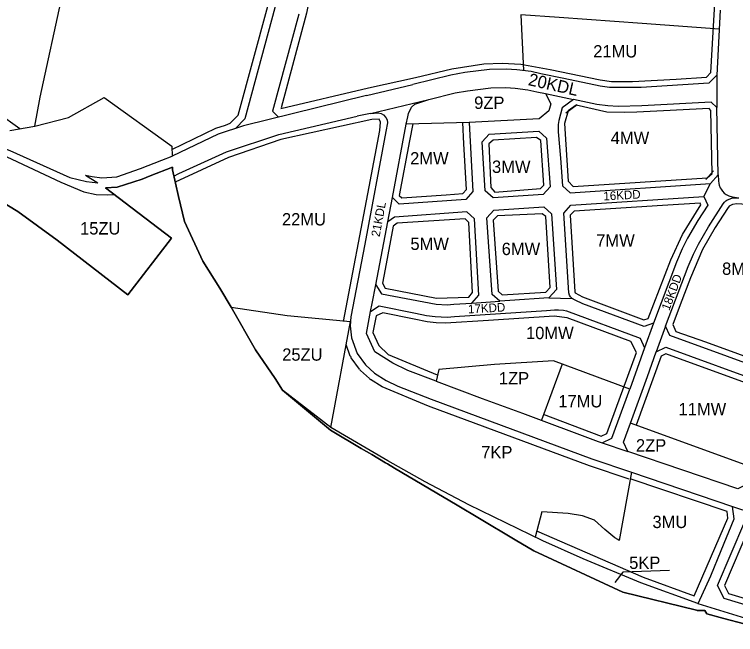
# Model space of a CAD drawing. Extents: x 7428203 to 7432868, y 5542672 to 5545406.
# Drawn here: x 7431420 to 7432004, y 5542894 to 5543396 of the extents above; entities that cross this region are included whole.
import ezdxf

# ---------------------------------------------------------------- set-up
doc = ezdxf.new("R2010")
doc.units = 0
for name, color, linetype in [('__LEGENDA_RAMKA_LOGO_PODZIAŁKA', 7, 'Continuous'), ('_GRANICA_MIASTA', 7, 'Continuous'), ('granicaBulwary', 7, 'Continuous'), ('MPZP_uchwalone_nieobowiazujace jeszcze_SZRAF', 7, 'Continuous')]:
    doc.layers.add(name, color=color, linetype=linetype)

msp = doc.modelspace()

# ---------------------------------------------------------------- linework, layer by layer
at = {"layer": '__LEGENDA_RAMKA_LOGO_PODZIAŁKA'}
msp.add_lwpolyline([(7431389.74, 5543255.95), (7431422.59, 5543236.25), (7431454.36, 5543213.02), (7431511.7, 5543168.81), (7431547.16, 5543214.78), (7431493.62, 5543255.54), (7431503.11, 5543255.89), (7431523.35, 5543262.55), (7431529.68, 5543265.09), (7431547.71, 5543272.32), (7431547.71, 5543271.92), (7431547.72, 5543271.35), (7431547.75, 5543269.92), (7431552.77, 5543248.55), (7431557.55, 5543228.24), (7431572.47, 5543195.93), (7431586.13, 5543174.25), (7431595.28, 5543158.86), (7431615.19, 5543124.31), (7431630.97, 5543100.97), (7431637.05, 5543091.63), (7431675.9, 5543059.21), (7431700.89, 5543044.38), (7431709.41, 5543039.33), (7431720.58, 5543032.7), (7431722.11, 5543031.79), (7431727.75, 5543028.47), (7431778.7, 5542998.39), (7431796.77, 5542987.57), (7431825.57, 5542970.33), (7431840.69, 5542961.29), (7431912.76, 5542927.96), (7431972.47, 5542913.23), (7431973.07, 5542913.08), (7431979.3, 5542912.96), (7431980.87, 5542910.28), (7431994.8, 5542906.65), (7432011.22, 5542902.36)], dxfattribs=at)
at = {"layer": '_GRANICA_MIASTA'}
for p, q in [((7431650.15, 5543396.15), (7431628.87, 5543317.63)), ((7431991.84, 5543399.38), (7431988.98, 5543346.68)), ((7431784.79, 5543349.01), (7431773.48, 5543346.73)), ((7431804.81, 5543351.43), (7431784.79, 5543349.01)), ((7431818.35, 5543351.62), (7431804.81, 5543351.43)), ((7431826.9, 5543351.11), (7431818.35, 5543351.62)), ((7431838.44, 5543349.6), (7431826.9, 5543351.11)), ((7431846.26, 5543347.95), (7431838.44, 5543349.6)), ((7431865.06, 5543343.99), (7431846.26, 5543347.95)), ((7431773.48, 5543346.73), (7431742.73, 5543339.14)), ((7431894.42, 5543337.81), (7431865.06, 5543343.99)), ((7431988.98, 5543346.68), (7431982.63, 5543340.29)), ((7431704.98, 5543330.36), (7431742.73, 5543339.14)), ((7431787.04, 5543334.17), (7431805.82, 5543336.44)), ((7431805.82, 5543336.44), (7431818.01, 5543336.62)), ((7431818.01, 5543336.62), (7431825.48, 5543336.17)), ((7431825.48, 5543336.17), (7431835.92, 5543334.8)), ((7431902.1, 5543336.77), (7431894.42, 5543337.81)), ((7431927.62, 5543336.75), (7431902.1, 5543336.77)), ((7431982.63, 5543340.29), (7431927.62, 5543336.75)), ((7431704.98, 5543330.36), (7431605.47, 5543305.81)), ((7431755.54, 5543326.92), (7431776.87, 5543332.31)), ((7431776.87, 5543332.31), (7431787.04, 5543334.17)), ((7431835.92, 5543334.8), (7431843.17, 5543333.27)), ((7431843.17, 5543333.27), (7431850.09, 5543331.81)), ((7431850.09, 5543331.81), (7431872.83, 5543327.03)), ((7431850.09, 5543331.81), (7431854.37, 5543323.64)), ((7431708.38, 5543315.74), (7431755.54, 5543326.92)), ((7431744.38, 5543323.34), (7431755.54, 5543326.92)), ((7431739.11, 5543315.76), (7431741.63, 5543320.87)), ((7431741.63, 5543320.87), (7431744.38, 5543323.34)), ((7431854.37, 5543323.64), (7431852.77, 5543317.91)), ((7431628.96, 5543317.55), (7431633.8, 5543312.8)), ((7431708.38, 5543315.74), (7431697.64, 5543313.47)), ((7431708.38, 5543315.74), (7431714.42, 5543316.36)), ((7431714.42, 5543316.36), (7431716.87, 5543315.78)), ((7431716.87, 5543315.78), (7431718.9, 5543314.51)), ((7431718.9, 5543314.51), (7431720.73, 5543312.55)), ((7431720.73, 5543312.55), (7431721.82, 5543310.61)), ((7431737.2, 5543307.03), (7431738.59, 5543313.05)), ((7431738.59, 5543313.05), (7431739.11, 5543315.76)), ((7431852.77, 5543317.91), (7431845.04, 5543311.44)), ((7431722.15, 5543308.2), (7431720.88, 5543301)), ((7431721.82, 5543310.61), (7431722.15, 5543308.2)), ((7431726.17, 5543247.73), (7431737.2, 5543307.03)), ((7431788.19, 5543308.51), (7431737.2, 5543307.03)), ((7431845.04, 5543311.44), (7431788.19, 5543308.51)), ((7431788.19, 5543308.51), (7431791.27, 5543252.4)), ((7431605.47, 5543305.81), (7431584.92, 5543299.03)), ((7431720.88, 5543301), (7431703.66, 5543209.89)), ((7431584.92, 5543299.03), (7431547.5, 5543281)), ((7431547.71, 5543272.32), (7431529.68, 5543265.09)), ((7431547.71, 5543271.92), (7431547.71, 5543272.32)), ((7431547.72, 5543271.35), (7431547.71, 5543271.92)), ((7431547.75, 5543269.92), (7431547.72, 5543271.35)), ((7431477.33, 5543265.7), (7431487.44, 5543259.4)), ((7431552.77, 5543248.55), (7431547.75, 5543269.92)), ((7431523.35, 5543262.55), (7431503.11, 5543255.89)), ((7431529.68, 5543265.09), (7431523.35, 5543262.55)), ((7431422.59, 5543236.25), (7431389.74, 5543255.95)), ((7431503.11, 5543255.89), (7431493.62, 5543255.54)), ((7431493.62, 5543255.54), (7431547.16, 5543214.78)), ((7431978.52, 5543248.35), (7431983.83, 5543258.99)), ((7431557.55, 5543228.24), (7431552.77, 5543248.55)), ((7431791.27, 5543252.4), (7431785.69, 5543245.99)), ((7431722.36, 5543227.81), (7431726.17, 5543247.73)), ((7431731.52, 5543242.13), (7431726.17, 5543247.73)), ((7431785.69, 5543245.99), (7431731.52, 5543242.13)), ((7431454.36, 5543213.02), (7431422.59, 5543236.25)), ((7431572.47, 5543195.93), (7431557.55, 5543228.24)), ((7431712.61, 5543176.78), (7431722.36, 5543227.81)), ((7431511.7, 5543168.81), (7431454.36, 5543213.02)), ((7431547.16, 5543214.78), (7431511.7, 5543168.81)), ((7431703.66, 5543209.89), (7431692.26, 5543150.94)), ((7431586.13, 5543174.25), (7431572.47, 5543195.93)), ((7431595.28, 5543158.86), (7431586.13, 5543174.25)), ((7431709.72, 5543161.69), (7431712.61, 5543176.78)), ((7431708.45, 5543155.18), (7431709.72, 5543161.69)), ((7431615.19, 5543124.31), (7431595.28, 5543158.86)), ((7431705.12, 5543137.59), (7431708.45, 5543155.18)), ((7431676.21, 5543061.35), (7431691.99, 5543147.31)), ((7431937.69, 5543145.87), (7431930.46, 5543125.87)), ((7431711.76, 5543122.53), (7431705.12, 5543137.59)), ((7431630.97, 5543100.97), (7431615.19, 5543124.31)), ((7431863.58, 5543112.73), (7431846.95, 5543067.25)), ((7431637.05, 5543091.63), (7431630.97, 5543100.97)), ((7431721, 5543099.47), (7431730.42, 5543094.82)), ((7431675.9, 5543059.21), (7431637.05, 5543091.63)), ((7431730.42, 5543094.82), (7431757.44, 5543084.31)), ((7431757.44, 5543084.31), (7431887.8, 5543035.86)), ((7432017.85, 5543028.79), (7431919, 5543064.95)), ((7431700.89, 5543044.38), (7431675.9, 5543059.21)), ((7431709.41, 5543039.33), (7431700.89, 5543044.38)), ((7431896.06, 5543048.9), (7431916.9, 5543041.85)), ((7431720.58, 5543032.7), (7431709.41, 5543039.33)), ((7431722.11, 5543031.79), (7431720.58, 5543032.7)), ((7431727.75, 5543028.47), (7431722.11, 5543031.79)), ((7431887.8, 5543035.86), (7431919.79, 5543025.03)), ((7431778.7, 5542998.39), (7431727.75, 5543028.47)), ((7431919.79, 5543025.03), (7431909.97, 5542969.91)), ((7431796.77, 5542987.57), (7431778.7, 5542998.39)), ((7432001.68, 5542997.32), (7432063.09, 5542976.74)), ((7431825.57, 5542970.33), (7431796.77, 5542987.57)), ((7431989.67, 5542933.23), (7432011.78, 5542985.25)), ((7431840.69, 5542961.29), (7431825.57, 5542970.33)), ((7431912.76, 5542927.96), (7431840.69, 5542961.29)), ((7431995.04, 5542922.73), (7431989.67, 5542933.23)), ((7431972.47, 5542913.23), (7431912.76, 5542927.96)), ((7432019.53, 5542915.43), (7431995.04, 5542922.73)), ((7431973.07, 5542913.08), (7431972.47, 5542913.23)), ((7431979.3, 5542912.96), (7431973.07, 5542913.08)), ((7431980.87, 5542910.28), (7431979.3, 5542912.96)), ((7431994.8, 5542906.65), (7431980.87, 5542910.28)), ((7432011.22, 5542902.36), (7431994.8, 5542906.65))]:
    msp.add_line(p, q, dxfattribs=at)
for points in [[(7431436.3, 5543305.53), (7431440.68, 5543328.86), (7431476.66, 5543495.49), (7431506.81, 5543625.52)], [(7431667.23, 5543590.08), (7431645.7, 5543477.8), (7431630.84, 5543401.36), (7431606.51, 5543311.31), (7431598.84, 5543303.62)], [(7431991, 5543383.88), (7431928.42, 5543388.5), (7431861.27, 5543393.45), (7431830.25, 5543395.73), (7431832.25, 5543350.41)], [(7431988.98, 5543346.68), (7431989.03, 5543320.57), (7431984.56, 5543324.99), (7431928.27, 5543321.77), (7431909.17, 5543321.34), (7431900.66, 5543321.83), (7431891.87, 5543323.02), (7431872.83, 5543327.03), (7431863.73, 5543320.36), (7431861.05, 5543309.9), (7431860.44, 5543306.88), (7431860.38, 5543306.1), (7431860.47, 5543300.79), (7431862.3, 5543279.55), (7431863.93, 5543256.98), (7431870.26, 5543251.36), (7431983.83, 5543258.99), (7431990.16, 5543266.02), (7431989.49, 5543292.86), (7431989.03, 5543320.57)], [(7431415.94, 5543301.93), (7431436.35, 5543305.54), (7431463.65, 5543312.41), (7431492.57, 5543328.57), (7431547.32, 5543289.35), (7431547.5, 5543281)], [(7431591.58, 5543284.69), (7431634.06, 5543298.65), (7431697.64, 5543313.47)], [(7431383.66, 5543294.77), (7431401.55, 5543290.86), (7431416.06, 5543285.83), (7431464.51, 5543263.85), (7431478.05, 5543260.69), (7431487.44, 5543259.4)], [(7431384.15, 5543294.67), (7431390.98, 5543291.05), (7431457.43, 5543259.96)], [(7431548.9, 5543265.04), (7431553.05, 5543267.04), (7431591.58, 5543284.69)], [(7431477.33, 5543265.7), (7431482.72, 5543264.73), (7431490.43, 5543263.67), (7431502.66, 5543264.27), (7431521.83, 5543271.16), (7431539.28, 5543278), (7431547.5, 5543281)], [(7431990.16, 5543266.02), (7431990.37, 5543261.06), (7431990.58, 5543259.1), (7431990.97, 5543257.51), (7431991.75, 5543255.57), (7431992.43, 5543254.34), (7431993.59, 5543252.77), (7431995.11, 5543251.25), (7431996.69, 5543250.09), (7431998.75, 5543249.03), (7432001.46, 5543248.23), (7432006.98, 5543247.37)], [(7431457.43, 5543259.96), (7431475.95, 5543252.27), (7431486.04, 5543250.05), (7431495.11, 5543249.75), (7431500.69, 5543250.16)], [(7431852.94, 5543166.25), (7431871.67, 5543165.86), (7431870.35, 5543167.08), (7431869.56, 5543168.57), (7431869.08, 5543170.32), (7431865.01, 5543235), (7431870.79, 5543241.37), (7431978.52, 5543248.35), (7431981.64, 5543241.54), (7431973.75, 5543229.07), (7431965.27, 5543214.61), (7431961.01, 5543205.95), (7431956.42, 5543195.38), (7431937.69, 5543145.87), (7431930.2, 5543143.04), (7431880.3, 5543161.59), (7431874.35, 5543164.47), (7431871.67, 5543165.86)], [(7432032.45, 5543106.16), (7431997.81, 5543118.94), (7431950.96, 5543135.72), (7431947.45, 5543143.42), (7431965.69, 5543191.62), (7431970.09, 5543201.75), (7431974.08, 5543209.86), (7431982.29, 5543223.86), (7431994.13, 5543242.58), (7431995.19, 5543243.87), (7431996.41, 5543244.83), (7431997.28, 5543245.45), (7431999.07, 5543246.35), (7432001.23, 5543246.99), (7432003.48, 5543247.42), (7432006.98, 5543247.37)], [(7431790.38, 5543162.09), (7431813.29, 5543163.58), (7431806.9, 5543169.18), (7431802.72, 5543231.14), (7431808.31, 5543237.5), (7431848.84, 5543240.01), (7431855.15, 5543234.39), (7431858.96, 5543173.07), (7431852.94, 5543166.25), (7431821.28, 5543164.1), (7431813.29, 5543163.58)], [(7431712.61, 5543176.78), (7431717.36, 5543169.7), (7431761.61, 5543161.14), (7431770.39, 5543160.8), (7431775.88, 5543161.15), (7431790.38, 5543162.09), (7431796.13, 5543168.48), (7431792.75, 5543230.45), (7431786.36, 5543236.01), (7431727.71, 5543231.83), (7431722.36, 5543227.81)], [(7431595.28, 5543158.86), (7431640.84, 5543152.09), (7431691.99, 5543147.31)], [(7431708.45, 5543155.18), (7431715.48, 5543159.88), (7431744.71, 5543153.96), (7431753.69, 5543152.14), (7431760.73, 5543151.17), (7431770.52, 5543150.78), (7431776.53, 5543151.17), (7431850.99, 5543156.01), (7431857.35, 5543156.63), (7431860.71, 5543156.74), (7431864.67, 5543156.37), (7431867.13, 5543155.82), (7431926.83, 5543133.62), (7431930.46, 5543125.87), (7431918.41, 5543092.32), (7431856.75, 5543115.27), (7431808.89, 5543112.26), (7431763.62, 5543108.23), (7431761.6, 5543098.78), (7431738.65, 5543107.49), (7431726.48, 5543113.5), (7431711.76, 5543122.53)], [(7431692.26, 5543150.94), (7431691.71, 5543143.67), (7431693.03, 5543134.07), (7431697.59, 5543121.2), (7431704.23, 5543111.96), (7431711.5, 5543105.36), (7431721, 5543099.47)], [(7431947.45, 5543143.42), (7431939.96, 5543122.74), (7431947.58, 5543126.31), (7432030.55, 5543096.2), (7432035.1, 5543088.13), (7432028.11, 5543060.23), (7432017.85, 5543028.79), (7432013.51, 5543015.49), (7432005.96, 5543011.7), (7431916.9, 5543041.85), (7431913.29, 5543049.4), (7431919, 5543064.95), (7431932.86, 5543102.67), (7431939.96, 5543122.74)], [(7431761.6, 5543098.78), (7431798.71, 5543084.7), (7431831.66, 5543073), (7431892.84, 5543049.99), (7431896.06, 5543048.9), (7431903.81, 5543052.61), (7431918.41, 5543092.32)], [(7431973.61, 5542918.72), (7431927.43, 5542935.57), (7431880.83, 5542955.06), (7431848.05, 5542969.53), (7431788, 5542998.67), (7431752.6, 5543017.22), (7431722.5, 5543034.34), (7431676.21, 5543061.35), (7431637.05, 5543091.63)], [(7431919.79, 5543025.03), (7432001.68, 5542997.32)], [(7431973.93, 5542918.62), (7431984.23, 5542941.05), (7431992.43, 5542961.69), (7432003.03, 5542987.3), (7432001.68, 5542997.32)], [(7431909.97, 5542969.91), (7431908.8, 5542970.62), (7431906.46, 5542972.01), (7431898.21, 5542978.82), (7431889.92, 5542986.2), (7431880.26, 5542989.77), (7431868.45, 5542991.54), (7431847.25, 5542993.09), (7431841.76, 5542972.58)], [(7431973.61, 5542918.72), (7432026.26, 5542902.45), (7432052.98, 5542896.69)]]:
    msp.add_lwpolyline(points, dxfattribs=at)
msp.add_lwpolyline([(7431804.45, 5543298.95), (7431844.68, 5543301.4), (7431851.1, 5543295.77), (7431853.95, 5543256.36), (7431848.3, 5543250), (7431807.64, 5543247.47), (7431801.24, 5543253.09), (7431798.95, 5543292.68)], close=True, dxfattribs=at)
msp.add_ellipse((7431629.16, 5543317.7), major_axis=(0.314, 0.013), ratio=0.643015, start_param=3.44605, end_param=3.966719, dxfattribs=at)
at = {"layer": 'granicaBulwary'}
msp.add_lwpolyline([(7431950.59, 5542945.57), (7431912.96, 5542944.04), (7431906.44, 5542935.84)], dxfattribs=at)
at = {"layer": 'MPZP_uchwalone_nieobowiazujace jeszcze_SZRAF'}
for p, q in [((7431984.1, 5543349.02), (7431988.54, 5543424.24)), ((7431774.35, 5543352), (7431800.26, 5543355.92)), ((7431800.26, 5543355.92), (7431815.15, 5543356.58)), ((7431815.15, 5543356.58), (7431830.13, 5543355.73)), ((7431830.13, 5543355.73), (7431853.94, 5543351.44)), ((7431744.68, 5543344.77), (7431774.35, 5543352)), ((7431853.94, 5543351.44), (7431894.43, 5543342.91)), ((7431980.59, 5543345.18), (7431984.1, 5543349.02)), ((7431365.58, 5543344.99), (7431424.16, 5543303.46)), ((7431706.78, 5543336.52), (7431744.68, 5543344.77)), ((7431894.43, 5543342.91), (7431903.59, 5543341.69)), ((7431903.59, 5543341.69), (7431920.61, 5543341.6)), ((7431920.61, 5543341.6), (7431955.99, 5543343.62)), ((7431955.99, 5543343.62), (7431980.59, 5543345.18)), ((7431635.66, 5543319.86), (7431706.78, 5543336.52)), ((7431866.68, 5543316.33), (7431875.79, 5543322.99)), ((7431980.12, 5543262.33), (7431986.44, 5543269.36)), ((7431691.93, 5543119.2), (7431688.57, 5543128.69)), ((7431699.35, 5543108.46), (7431692.72, 5543117.7)), ((7431707.46, 5543100.92), (7431700.19, 5543107.52)), ((7431717.84, 5543094.37), (7431708.34, 5543100.26)), ((7431755.35, 5543078.69), (7431717.84, 5543094.37)), ((7431885.71, 5543030.24), (7431755.35, 5543078.69)), ((7431917.87, 5543019.35), (7431885.88, 5543030.18))]:
    msp.add_line(p, q, dxfattribs=at)
for points in [[(7431594.59, 5543307.86), (7431601.14, 5543314.41), (7431625, 5543402.72), (7431639.8, 5543478.94), (7431661.34, 5543591.21)], [(7431694.1, 5543592.69), (7431674.64, 5543491.6), (7431660.37, 5543416.96), (7431656.51, 5543397.07), (7431635.8, 5543320.41)], [(7431547.39, 5543286.47), (7431583.04, 5543303.68), (7431590.91, 5543306.31), (7431594.59, 5543307.86)], [(7431686.51, 5543147.12), (7431707.36, 5543256.37), (7431715.97, 5543301.93), (7431716.56, 5543308.66), (7431715.25, 5543311.09), (7431709.41, 5543310.85), (7431635.75, 5543294.63), (7431593.15, 5543279.94), (7431549.9, 5543260.1)], [(7431742.58, 5543307.19), (7431739.87, 5543293.62), (7431731.52, 5543249.36), (7431733.81, 5543247.3), (7431769.63, 5543249.85), (7431783.27, 5543250.83), (7431786.15, 5543254.13), (7431784.03, 5543291.23), (7431783.19, 5543308.37)], [(7432034.39, 5543113.14), (7432043.73, 5543188.67), (7432048.44, 5543232.45), (7432044.91, 5543236.73), (7432009.4, 5543242.19), (7432005.32, 5543242.44), (7432001.75, 5543241.93), (7431999.15, 5543240.63), (7431997.6, 5543238.7), (7431987.79, 5543223.21), (7431977.48, 5543205.45), (7431967.63, 5543182.62), (7431959.31, 5543160.62), (7431953.35, 5543144.87), (7431955.89, 5543139.22), (7431979.8, 5543130.62), (7432031.84, 5543111.71), (7432034.42, 5543113.41)], [(7431899.93, 5543056.33), (7431923.81, 5543122.08), (7431919.28, 5543131.09), (7431867.71, 5543150.27), (7431857.2, 5543151.59), (7431804, 5543147.95), (7431769.07, 5543145.84), (7431761.65, 5543146.13), (7431754.37, 5543147), (7431743.62, 5543149.08), (7431718.39, 5543154.19), (7431712.87, 5543151.67), (7431710.34, 5543138.31), (7431714.98, 5543127.62), (7431722.6, 5543120.5), (7431762.28, 5543103.87)], [(7432013.15, 5543030.51), (7432029.77, 5543087.41), (7432027.1, 5543092.15), (7431947.8, 5543120.89), (7431943.97, 5543119.1), (7431923.69, 5543063.23)], [(7431848.27, 5543071.99), (7431895.3, 5543054.31), (7431899.93, 5543056.33)], [(7431997.52, 5542993.23), (7431918.84, 5543019.67)], [(7431842.83, 5542977.53), (7431929.29, 5542940.21), (7431970.57, 5542924.97), (7431997.9, 5542987.96), (7431997.34, 5542993.4)], [(7432023.88, 5542984.66), (7432015.52, 5542980.91), (7431995.17, 5542933.46), (7431998.58, 5542926.78), (7432020.96, 5542920.22), (7432052.26, 5542917.94), (7432057.44, 5542919.56), (7432066.42, 5542919.52), (7432164.7, 5542893.58)]]:
    msp.add_lwpolyline(points, dxfattribs=at)
for points in [[(7431913.93, 5543316.44), (7431899.83, 5543316.89), (7431874.9, 5543322.34), (7431868.64, 5543317.76), (7431865.7, 5543307.67), (7431868.67, 5543260.75), (7431872.52, 5543256.51), (7431981.16, 5543263.49), (7431985.13, 5543266.99), (7431984.07, 5543318.06), (7431982.7, 5543319.79), (7431945.82, 5543317.9), (7431924.13, 5543316.67)], [(7431846.48, 5543293.73), (7431842.86, 5543296.28), (7431807.79, 5543294.16), (7431804.18, 5543291.06), (7431805.75, 5543255.79), (7431809.01, 5543251.9), (7431846.1, 5543255.05), (7431848.75, 5543257.6)], [(7431976.06, 5543241.72), (7431975.54, 5543243.14), (7431944.93, 5543241.11), (7431873.44, 5543236.53), (7431870.14, 5543233.22), (7431874.05, 5543171.21), (7431874.3, 5543170.3), (7431880.24, 5543167.18), (7431929.79, 5543148.52), (7431933.41, 5543149.6), (7431951.72, 5543197.09), (7431961.25, 5543217.63)], [(7431729.84, 5543226.97), (7431726.79, 5543224.36), (7431720.12, 5543189.49), (7431717.97, 5543178.19), (7431720.29, 5543174.3), (7431761.75, 5543166.17), (7431787.94, 5543166.85), (7431791.03, 5543170.81), (7431787.94, 5543227.46), (7431785.1, 5543230.47)], [(7431811.27, 5543232.67), (7431807.67, 5543229.19), (7431811.74, 5543171.72), (7431815, 5543168.73), (7431850.47, 5543171), (7431853.89, 5543174.73), (7431850.37, 5543232.12), (7431847.57, 5543234.44)]]:
    msp.add_lwpolyline(points, close=True, dxfattribs=at)
for centre, radius, start, end in [((7431697.37, 5543121.11), 5.77, 199.32116, 216.2274), ((7431705, 5543112.67), 7.05, 216.65394, 226.9151), ((7431712.02, 5543106.08), 6.89, 228.54864, 237.71156)]:
    msp.add_arc(centre, radius, start, end, dxfattribs=at)

# ---------------------------------------------------------------- texts
at = {"layer": 'granicaBulwary'}
for s, p in [('21MU', (7431888.86, 5543361.06)), ('9ZP', (7431792.35, 5543319.41)), ('4MW', (7431903.05, 5543290.93)), ('2MW', (7431740.47, 5543274.38)), ('3MW', (7431806.83, 5543267.58)), ('22MU', (7431636.57, 5543224.98)), ('15ZU', (7431472.91, 5543217.66)), ('5MW', (7431740.67, 5543205.16)), ('7MW', (7431891.31, 5543207.84)), ('6MW', (7431814.66, 5543201.01)), ('8MW', (7431993.29, 5543184.98)), ('10MW', (7431834.39, 5543132.89)), ('25ZU', (7431636.74, 5543115.43)), ('1ZP', (7431812.39, 5543096.23)), ('17MU', (7431860.57, 5543077.59)), ('11MW', (7431958.01, 5543071.24)), ('2ZP', (7431923.5, 5543041.86)), ('7KP', (7431798.09, 5543036.3)), ('3MU', (7431936.87, 5542979.85)), ('5KP', (7431918, 5542946.77))]:
    msp.add_text(s, height=10, dxfattribs=at).set_placement(p)
for s, height, rotation, p in [('20KDL', 10, 347.32198, (7431835.57, 5543338.76)), ('16KDD', 7, 3.15989, (7431897.29, 5543245.21)), ('21KDL', 7, 79.46419, (7431715.68, 5543215.34)), ('18KDD', 7, 69.42474, (7431950.47, 5543155.57)), ('17KDD', 7, 3.15989, (7431787.59, 5543153.71))]:
    msp.add_text(s, height=height, rotation=rotation, dxfattribs=at).set_placement(p)

doc.saveas('drawing.dxf')
